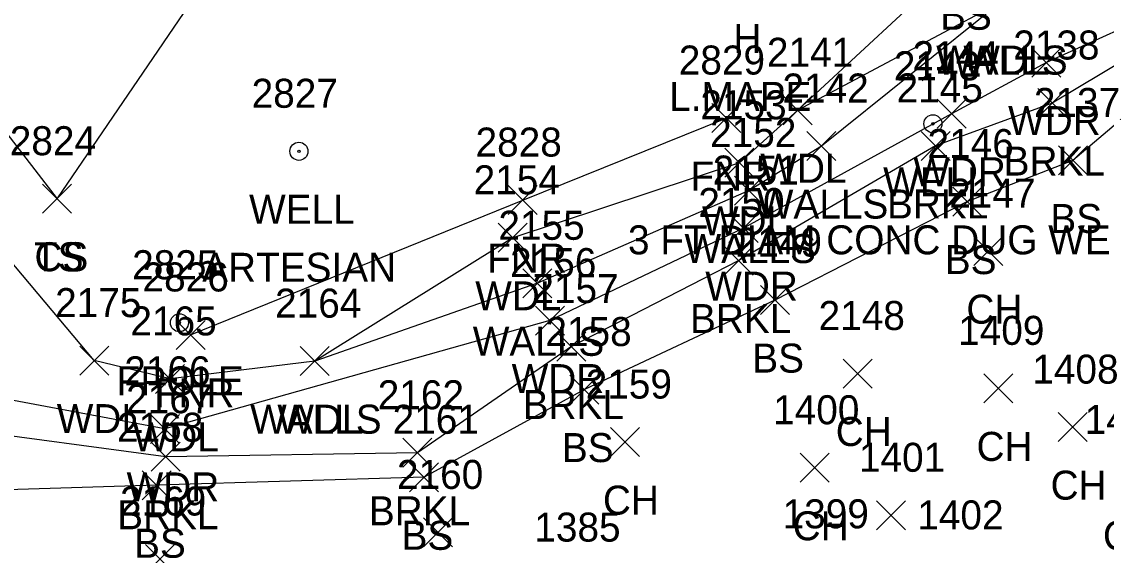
# Model space of a CAD drawing. Extents: x 1499292 to 1501024, y 534584 to 538043.
# Drawn here: x 1499706.6 to 1499781.4, y 537627.9 to 537664.7 of the extents above; entities that cross this region are included whole.
import ezdxf

# ---------------------------------------------------------------- set-up
doc = ezdxf.new("R2010")
doc.units = 0
for name, color, linetype in [('L_A', 7, 'Continuous'), ('L_C', 7, 'Continuous'), ('L_I', 7, 'Continuous'), ('L_TIC', 7, 'Continuous'), ('LAWA', 7, 'Continuous'), ('LAWE', 7, 'Continuous'), ('LELB', 7, 'Continuous'), ('LFNC', 7, 'Continuous'), ('LFP', 7, 'Continuous'), ('LWS', 7, 'Continuous'), ('U_A', 7, 'Continuous'), ('U_C', 7, 'Continuous'), ('U_I', 7, 'Continuous'), ('UWW', 7, 'Continuous')]:
    doc.layers.add(name, color=color, linetype=linetype)

msp = doc.modelspace()

# ---------------------------------------------------------------- linework, layer by layer
at = {"layer": 'L_TIC'}
for points in [[(1499776.304, 537660.837), (1499778.304, 537662.837)], [(1499778.304, 537660.837), (1499776.304, 537662.837)], [(1499776.71, 537658.051), (1499778.71, 537660.051)], [(1499778.71, 537658.051), (1499776.71, 537660.051)], [(1499759.161, 537657.549), (1499761.161, 537659.549)], [(1499761.161, 537657.549), (1499759.161, 537659.549)], [(1499769.764, 537657.315), (1499771.764, 537659.315)], [(1499771.764, 537657.315), (1499769.764, 537659.315)], [(1499754.224, 537657.014), (1499756.224, 537659.014)], [(1499756.224, 537657.014), (1499754.224, 537659.014)], [(1499760.796, 537655.084), (1499762.796, 537657.084)], [(1499762.796, 537655.084), (1499760.796, 537657.084)], [(1499768.667, 537655.093), (1499770.667, 537657.093)], [(1499770.667, 537655.093), (1499768.667, 537657.093)], [(1499755.138, 537653.928), (1499757.138, 537655.928)], [(1499757.138, 537653.928), (1499755.138, 537655.928)], [(1499778.135, 537654.089), (1499780.135, 537656.089)], [(1499780.135, 537654.089), (1499778.135, 537656.089)], [(1499755.809, 537652.017), (1499757.809, 537654.017)], [(1499757.809, 537652.017), (1499755.809, 537654.017)], [(1499708.086, 537651.452), (1499710.086, 537653.452)], [(1499710.086, 537651.452), (1499708.086, 537653.452)], [(1499708.086, 537651.452), (1499710.086, 537653.452)], [(1499710.086, 537651.452), (1499708.086, 537653.452)], [(1499740.202, 537651.359), (1499742.202, 537653.359)], [(1499742.202, 537651.359), (1499740.202, 537653.359)], [(1499770.857, 537651.255), (1499772.857, 537653.255)], [(1499772.857, 537651.255), (1499770.857, 537653.255)], [(1499755.419, 537649.428), (1499757.419, 537651.428)], [(1499757.419, 537649.428), (1499755.419, 537651.428)], [(1499739.504, 537648.758), (1499741.504, 537650.758)], [(1499741.504, 537648.758), (1499739.504, 537650.758)], [(1499772.297, 537647.838), (1499774.297, 537649.838)], [(1499774.297, 537647.838), (1499772.297, 537649.838)], [(1499755.087, 537647.189), (1499757.087, 537649.189)], [(1499757.087, 537647.189), (1499755.087, 537649.189)], [(1499741.21, 537645.621), (1499743.21, 537647.621)], [(1499743.21, 537645.621), (1499741.21, 537647.621)], [(1499757.583, 537644.464), (1499759.583, 537646.464)], [(1499759.583, 537644.464), (1499757.583, 537646.464)], [(1499742.071, 537643.05), (1499744.071, 537645.05)], [(1499744.071, 537643.05), (1499742.071, 537645.05)], [(1499717.293, 537642.059), (1499719.293, 537644.059)], [(1499719.293, 537642.059), (1499717.293, 537644.059)], [(1499743.553, 537641.256), (1499745.553, 537643.256)], [(1499745.553, 537641.256), (1499743.553, 537643.256)], [(1499710.646, 537640.29), (1499712.646, 537642.29)], [(1499712.646, 537640.29), (1499710.646, 537642.29)], [(1499725.858, 537640.254), (1499727.858, 537642.254)], [(1499727.858, 537640.254), (1499725.858, 537642.254)], [(1499725.858, 537640.254), (1499727.858, 537642.254)], [(1499727.858, 537640.254), (1499725.858, 537642.254)], [(1499763.29, 537639.402), (1499765.29, 537641.402)], [(1499765.29, 537639.402), (1499763.29, 537641.402)], [(1499715.884, 537639.029), (1499717.884, 537641.029)], [(1499717.884, 537639.029), (1499715.884, 537641.029)], [(1499744.452, 537638.294), (1499746.452, 537640.294)], [(1499746.452, 537638.294), (1499744.452, 537640.294)], [(1499772.999, 537638.377), (1499774.999, 537640.377)], [(1499774.999, 537638.377), (1499772.999, 537640.377)], [(1499715.518, 537635.585), (1499717.518, 537637.585)], [(1499717.518, 537635.585), (1499715.518, 537637.585)], [(1499778.106, 537635.704), (1499780.106, 537637.704)], [(1499780.106, 537635.704), (1499778.106, 537637.704)], [(1499747.237, 537634.674), (1499749.237, 537636.674)], [(1499749.237, 537634.674), (1499747.237, 537636.674)], [(1499715.584, 537633.663), (1499717.584, 537635.663)], [(1499717.584, 537633.663), (1499715.584, 537635.663)], [(1499732.938, 537633.936), (1499734.938, 537635.936)], [(1499734.938, 537633.936), (1499732.938, 537635.936)], [(1499760.32, 537632.903), (1499762.32, 537634.903)], [(1499762.32, 537632.903), (1499760.32, 537634.903)], [(1499733.398, 537632.246), (1499735.398, 537634.246)], [(1499735.398, 537632.246), (1499733.398, 537634.246)], [(1499714.956, 537631.699), (1499716.956, 537633.699)], [(1499716.956, 537631.699), (1499714.956, 537633.699)], [(1499765.581, 537629.627), (1499767.581, 537631.627)], [(1499767.581, 537629.627), (1499765.581, 537631.627)], [(1499734.351, 537628.444), (1499736.351, 537630.444)], [(1499736.351, 537628.444), (1499734.351, 537630.444)], [(1499715.175, 537626.612), (1499717.175, 537628.612)], [(1499717.175, 537626.612), (1499715.175, 537628.612)]]:
    msp.add_lwpolyline(points, dxfattribs=at)
at = {"layer": 'LAWA'}
for points in [[(1499794.252, 537673.216), (1499784.112, 537668.524), (1499774.16, 537666.013), (1499760.161, 537658.549), (1499756.138, 537654.928), (1499740.504, 537649.758), (1499726.858, 537641.254), (1499716.884, 537640.029), (1499711.646, 537641.29), (1499703.308, 537651.197), (1499688.979, 537659.909), (1499670.84, 537674.411)], [(1499794.252, 537673.216), (1499786.256, 537665.901), (1499777.304, 537661.837), (1499770.764, 537658.315), (1499756.419, 537650.428), (1499743.071, 537644.05), (1499716.518, 537636.585), (1499702.504, 537639.211), (1499689.259, 537643.126), (1499678.136, 537647.699), (1499664.493, 537654.207)]]:
    msp.add_lwpolyline(points, dxfattribs=at)
at = {"layer": 'LAWE'}
msp.add_lwpolyline([(1499799.843, 537680.234), (1499787.978, 537665.175), (1499777.71, 537659.051), (1499769.667, 537656.093), (1499756.087, 537648.189), (1499744.553, 537642.256), (1499733.938, 537634.936), (1499716.584, 537634.663), (1499702.206, 537636.578)], dxfattribs=at)
at = {"layer": 'LELB'}
for points in [[(1499931.33, 537841.299), (1499922.805, 537827.368), (1499912.716, 537807.848), (1499905.961, 537796.116), (1499895.821, 537778.011), (1499880.547, 537762.563), (1499870.857, 537749.776), (1499857.652, 537732.091), (1499849.894, 537720.064), (1499839.898, 537710.152), (1499830.869, 537699.252), (1499819.753, 537691.274), (1499813.247, 537682.443), (1499807.235, 537678.729), (1499801.402, 537680.954), (1499789.916, 537664.219), (1499779.135, 537655.089), (1499771.857, 537652.255), (1499758.583, 537645.464), (1499745.452, 537639.294), (1499734.398, 537633.246), (1499715.956, 537632.699), (1499700.464, 537632.224)], [(1499687.017, 537701.096), (1499696.713, 537675.684), (1499703.218, 537660.051), (1499709.086, 537652.452)], [(1499709.086, 537652.452), (1499727.251, 537679.109), (1499730.18, 537700.095)], [(1499771.532, 537669.102), (1499760.161, 537658.549)]]:
    msp.add_lwpolyline(points, dxfattribs=at)
at = {"layer": 'LFNC'}
msp.add_lwpolyline([(1499718.293, 537643.059), (1499741.202, 537652.359), (1499755.224, 537658.014)], dxfattribs=at)
at = {"layer": 'LFP'}
for radius in [0.625, 0.0833]:
    msp.add_circle((1499717.524, 537643.902), radius, dxfattribs=at)
at = {"layer": 'LWS'}
msp.add_lwpolyline([(1499774.16, 537666.013), (1499761.796, 537656.084), (1499756.809, 537653.017), (1499742.21, 537646.621), (1499726.858, 537641.254)], dxfattribs=at)
at = {"layer": 'UWW'}
for centre, radius in [((1499769.478, 537657.618), 0.625), ((1499769.478, 537657.618), 0.0833), ((1499725.762, 537655.723), 0.625), ((1499725.762, 537655.723), 0.0833)]:
    msp.add_circle(centre, radius, dxfattribs=at)

# ---------------------------------------------------------------- texts
at = {"layer": 'L_A'}
for s, p in [('BS', (1499769.973, 537664.102)), ('H', (1499755.72, 537662.508)), ('WALLS', (1499769.703, 537661.013)), ('WDL', (1499771.577, 537661.013)), ('WDR', (1499774.666, 537656.837)), ('WDL', (1499757.579, 537653.549)), ('BRKL', (1499774.356, 537654.051)), ('FNR', (1499752.759, 537653.014)), ('WDR', (1499768.126, 537653.315)), ('WALLS', (1499757.339, 537651.084)), ('BRKL', (1499766.313, 537651.093)), ('WDL', (1499753.555, 537649.928)), ('BS', (1499777.576, 537650.089)), ('TS', (1499707.495, 537647.452)), ('CS', (1499707.527, 537647.452)), ('WALLS', (1499752.352, 537648.017)), ('FNR', (1499738.738, 537647.359)), ('BS', (1499770.298, 537647.255)), ('WDR', (1499753.781, 537645.428)), ('WDL', (1499737.921, 537644.758)), ('CH', (1499771.786, 537643.838)), ('BRKL', (1499752.732, 537643.189)), ('WALLS', (1499737.753, 537641.621)), ('BS', (1499757.024, 537640.464)), ('FPOLE', (1499713.194, 537638.902)), ('WDR', (1499740.433, 537639.05)), ('FNR', (1499715.829, 537638.059)), ('BRKL', (1499741.198, 537637.256)), ('WDL', (1499709.064, 537636.29)), ('WALLS', (1499722.401, 537636.254)), ('WDL', (1499724.275, 537636.254)), ('WDL', (1499714.301, 537635.029)), ('CH', (1499762.778, 537635.402)), ('BS', (1499743.893, 537634.294)), ('CH', (1499772.487, 537634.377)), ('WDR', (1499713.88, 537631.585)), ('CH', (1499777.594, 537631.704)), ('CH', (1499746.726, 537630.674)), ('BRKL', (1499713.23, 537629.663)), ('BRKL', (1499730.584, 537629.936)), ('CH', (1499759.809, 537628.903)), ('BS', (1499732.839, 537628.246)), ('CH', (1499781.203, 537628.235)), ('BS', (1499714.397, 537627.699))]:
    msp.add_text(s, height=2, dxfattribs=at).set_placement(p)
at = {"layer": 'L_C'}
msp.add_text('L.MAPE', height=2, dxfattribs=at).set_placement((1499751.295, 537658.508))
at = {"layer": 'L_I'}
for s, p in [('2138', (1499775.017, 537662.051)), ('2829', (1499751.956, 537661.014)), ('2141', (1499758.035, 537661.549)), ('2144', (1499768.071, 537661.315)), ('2142', (1499759.103, 537659.084)), ('2145', (1499766.975, 537659.093)), ('2153', (1499753.445, 537657.928)), ('2137', (1499776.442, 537658.089)), ('2152', (1499754.116, 537656.017)), ('2824', (1499705.826, 537655.452)), ('2824', (1499705.826, 537655.452)), ('2828', (1499737.942, 537655.359)), ('2146', (1499769.109, 537655.255)), ('2151', (1499754.293, 537653.428)), ('2154', (1499737.811, 537652.758)), ('2150', (1499753.307, 537651.189)), ('2147', (1499770.604, 537651.838)), ('2155', (1499739.517, 537649.621)), ('2149', (1499755.882, 537648.464)), ('2825', (1499714.264, 537646.902)), ('2156', (1499740.323, 537647.05)), ('2826', (1499714.979, 537646.059)), ('2157', (1499741.86, 537645.256)), ('2175', (1499708.953, 537644.29)), ('2164', (1499724.118, 537644.254)), ('2164', (1499724.118, 537644.254)), ('2165', (1499714.144, 537643.029)), ('2148', (1499761.597, 537643.402)), ('2158', (1499742.759, 537642.294)), ('1409', (1499771.22, 537642.377)), ('2166', (1499713.722, 537639.585)), ('1408', (1499776.335, 537639.704)), ('2159', (1499745.537, 537638.674)), ('2162', (1499731.198, 537637.936)), ('2167', (1499713.844, 537637.663)), ('2161', (1499732.224, 537636.246)), ('1400', (1499758.462, 537636.903)), ('1407', (1499779.943, 537636.235)), ('2168', (1499713.216, 537635.699)), ('1401', (1499764.377, 537633.627)), ('2160', (1499732.524, 537632.444)), ('2169', (1499713.427, 537630.612)), ('1399', (1499759.114, 537629.728)), ('1402', (1499768.402, 537629.654)), ('1385', (1499741.994, 537628.813))]:
    msp.add_text(s, height=2, dxfattribs=at).set_placement(p)
at = {"layer": 'U_A'}
for p in [(1499766.045, 537652.618), (1499722.329, 537650.723)]:
    msp.add_text('WELL', height=2, dxfattribs=at).set_placement(p)
at = {"layer": 'U_C'}
for s, p in [('3 FT DIAM CONC DUG WELL', (1499748.454, 537648.618)), ('ARTESIAN', (1499719.093, 537646.723))]:
    msp.add_text(s, height=2, dxfattribs=at).set_placement(p)
at = {"layer": 'U_I'}
for s, p in [('2143', (1499766.785, 537660.618)), ('2827', (1499722.502, 537658.723))]:
    msp.add_text(s, height=2, dxfattribs=at).set_placement(p)

doc.saveas('drawing.dxf')
